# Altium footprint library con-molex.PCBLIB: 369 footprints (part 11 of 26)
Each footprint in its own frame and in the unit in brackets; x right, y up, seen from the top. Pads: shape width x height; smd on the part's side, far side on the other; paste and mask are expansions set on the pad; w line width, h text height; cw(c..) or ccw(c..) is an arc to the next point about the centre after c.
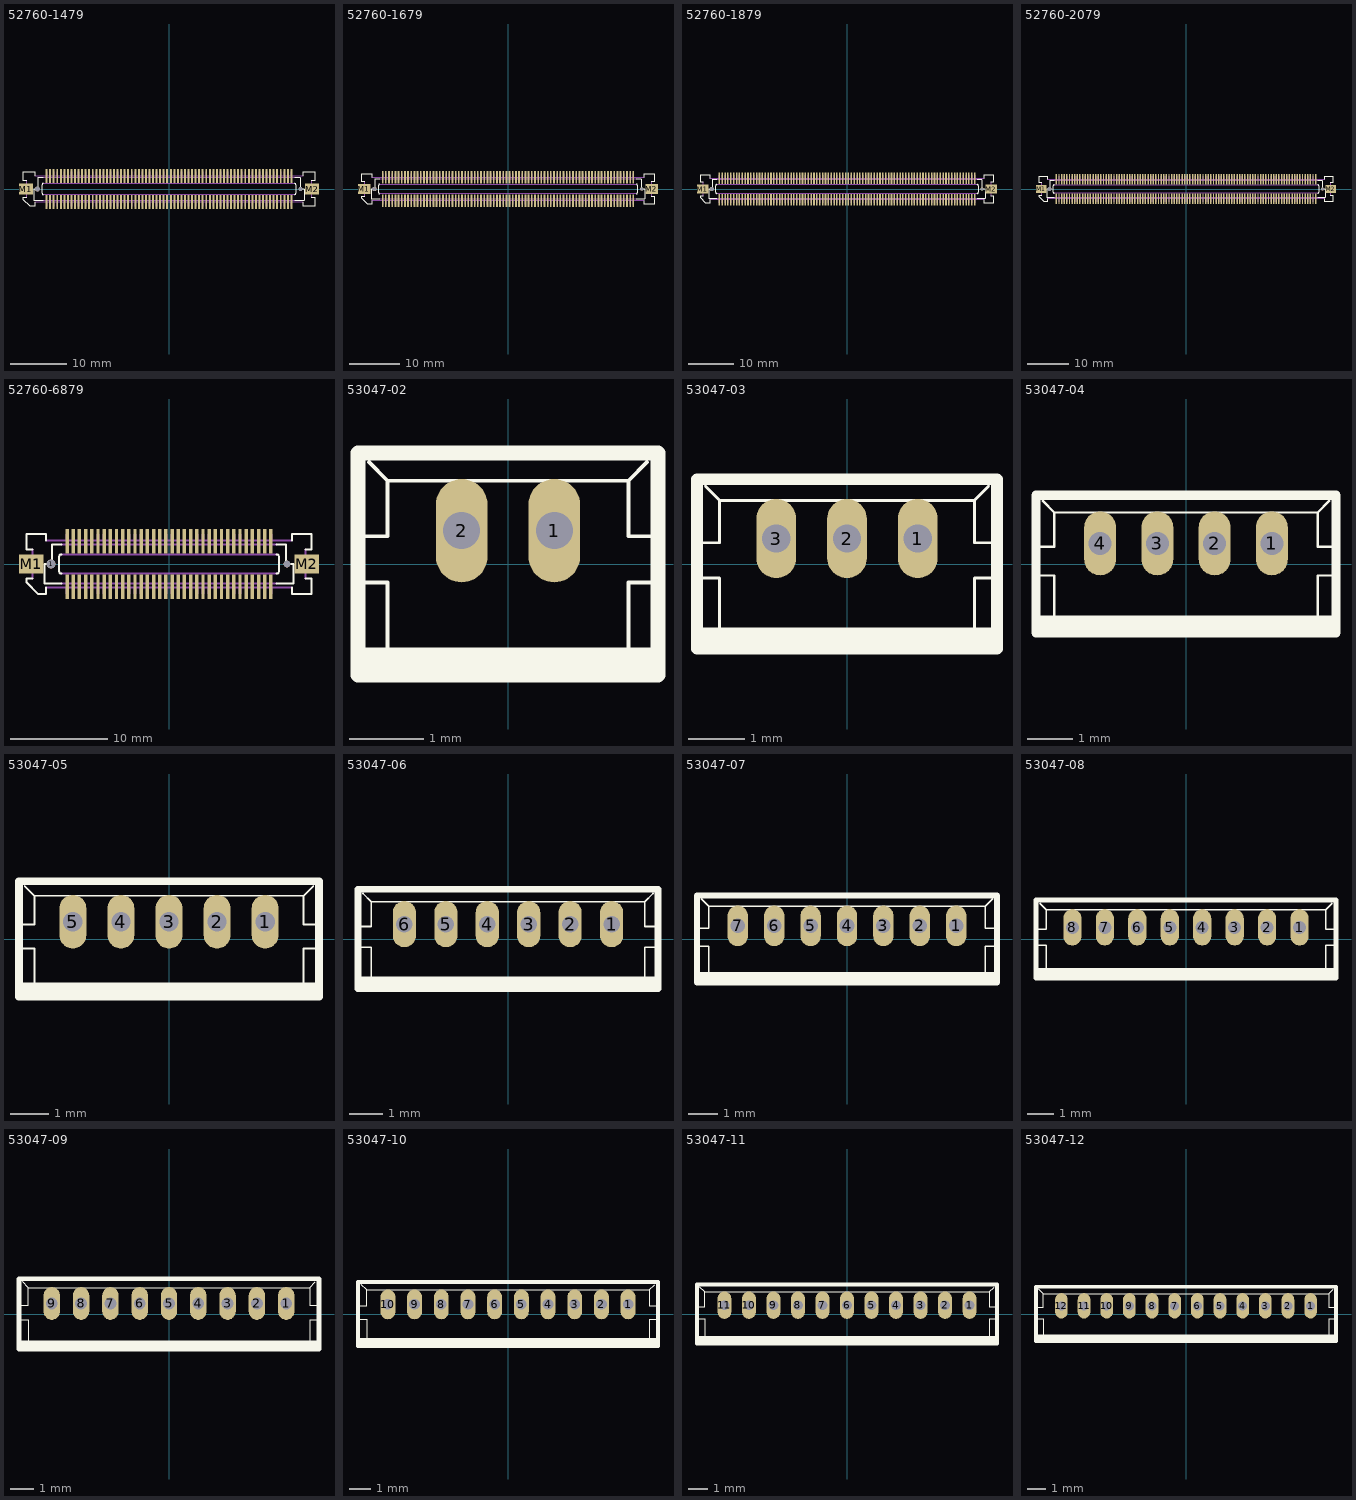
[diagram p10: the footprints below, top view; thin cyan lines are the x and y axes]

## 52760-1479 [mm]
pads (144):
  round 0.9 hole 0.9: 1(-23.56,0)
  rect 0.35x2.5 smd: 1(-21.907,-2.35) 2(-21.907,2.35) 3(-21.273,-2.35) 4(-21.273,2.35) 5(-20.637,-2.35) 6(-20.637,2.35) 7(-20.002,-2.35) 8(-20.002,2.35) 9(-19.367,-2.35) 10(-19.367,2.35) 11(-18.732,-2.35) 12(-18.732,2.35) 13(-18.098,-2.35) 14(-18.098,2.35) 15(-17.462,-2.35) 16(-17.462,2.35) 17(-16.828,-2.35) 18(-16.828,2.35) 19(-16.192,-2.35) 20(-16.192,2.35) 21(-15.557,-2.35) 22(-15.557,2.35) 23(-14.922,-2.35) 24(-14.922,2.35) 25(-14.287,-2.35) 26(-14.287,2.35) 27(-13.652,-2.35) 28(-13.652,2.35) 29(-13.018,-2.35) 30(-13.018,2.35) 31(-12.383,-2.35) 32(-12.383,2.35) 33(-11.747,-2.35) 34(-11.747,2.35) 35(-11.112,-2.35) 36(-11.112,2.35) 37(-10.477,-2.35) 38(-10.477,2.35) 39(-9.842,-2.35) 40(-9.842,2.35) 41(-9.207,-2.35) 42(-9.207,2.35) 43(-8.572,-2.35) 44(-8.572,2.35) 45(-7.938,-2.35) 46(-7.938,2.35) 47(-7.302,-2.35) 48(-7.302,2.35) 49(-6.667,-2.35) 50(-6.667,2.35) 51(-6.032,-2.35) 52(-6.032,2.35) 53(-5.397,-2.35) 54(-5.397,2.35) 55(-4.763,-2.35) 56(-4.763,2.35) 57(-4.127,-2.35) 58(-4.127,2.35) 59(-3.492,-2.35) 60(-3.492,2.35) 61(-2.857,-2.35) 62(-2.857,2.35) 63(-2.222,-2.35) 64(-2.222,2.35) 65(-1.587,-2.35) 66(-1.587,2.35) 67(-0.953,-2.35) 68(-0.953,2.35) 69(-0.318,-2.35) 70(-0.318,2.35) 71(0.318,-2.35) 72(0.318,2.35) 73(0.953,-2.35) 74(0.953,2.35) 75(1.587,-2.35) 76(1.587,2.35) 77(2.222,-2.35) 78(2.222,2.35) 79(2.857,-2.35) 80(2.857,2.35) 81(3.492,-2.35) 82(3.492,2.35) 83(4.127,-2.35) 84(4.127,2.35) 85(4.763,-2.35) 86(4.763,2.35) 87(5.397,-2.35) 88(5.397,2.35) 89(6.032,-2.35) 90(6.032,2.35) 91(6.667,-2.35) 92(6.667,2.35) 93(7.302,-2.35) 94(7.302,2.35) 95(7.938,-2.35) 96(7.938,2.35) 97(8.572,-2.35) 98(8.572,2.35) 99(9.207,-2.35) 100(9.207,2.35) 101(9.842,-2.35) 102(9.842,2.35) 103(10.477,-2.35) 104(10.477,2.35) 105(11.112,-2.35) 106(11.112,2.35) 107(11.747,-2.35) 108(11.747,2.35) 109(12.383,-2.35) 110(12.383,2.35) 111(13.018,-2.35) 112(13.018,2.35) 113(13.652,-2.35) 114(13.652,2.35) 115(14.287,-2.35) 116(14.287,2.35) 117(14.922,-2.35) 118(14.922,2.35) 119(15.557,-2.35) 120(15.557,2.35) 121(16.192,-2.35) 122(16.192,2.35) 123(16.828,-2.35) 124(16.828,2.35) 125(17.462,-2.35) 126(17.462,2.35) 127(18.098,-2.35) 128(18.098,2.35) 129(18.732,-2.35) 130(18.732,2.35) 131(19.367,-2.35) 132(19.367,2.35) 133(20.002,-2.35) 134(20.002,2.35) 135(20.637,-2.35) 136(20.637,2.35) 137(21.273,-2.35) 138(21.273,2.35) 139(21.907,-2.35) 140(21.907,2.35)
  round 0.7 hole 0.7: 1(23.56,0)
  rect 2.5x2 smd: M1(-25.6,0) M2(25.6,0)
Top Overlay:
  lines w0.203: -25.475,-1.5 -26.075,-1.5 -26.075,-1.9 -24.875,-3.1 -24.075,-3.1 -24.075,-2.4 ; -25.475,1.5 -26.075,1.5 -26.075,3.1 -24.075,3.1 -24.075,2.4 ; -22.475,-2 -24.225,-2 -24.225,0 -23.475,0 -23.475,2 -22.475,2 ; -22.475,-1 cw(c-22.475,-0.75) -22.725,-0.75 -22.725,0.75 cw(c-22.475,0.75) -22.475,1 ; 22.475,-2 24.225,-2 24.225,0 23.475,0 23.475,2 22.475,2 ; 22.475,-1 ccw(c22.475,-0.75) 22.725,-0.75 22.725,0.75 ccw(c22.475,0.75) 22.475,1 ; 24.075,-2.4 24.075,-3.1 26.075,-3.1 26.075,-1.5 25.475,-1.5 ; 24.075,2.4 24.075,3.1 26.075,3.1 26.075,1.5 25.475,1.5
Top Solder:
  rectangle: -22.107,-3.625 -21.708,-1.075
  region: -21.708,3.625 -22.107,3.625 -22.107,1.075 -21.708,1.075
  rectangle: -21.472,-3.625 -21.073,-1.075
  region: -21.073,3.625 -21.472,3.625 -21.472,1.075 -21.073,1.075
  rectangle: -20.837,-3.625 -20.438,-1.075
  region: -20.438,3.625 -20.837,3.625 -20.837,1.075 -20.438,1.075
  rectangle: -20.202,-3.625 -19.803,-1.075
  region: -19.803,3.625 -20.202,3.625 -20.202,1.075 -19.803,1.075
  rectangle: -19.567,-3.625 -19.168,-1.075
  region: -19.168,3.625 -19.567,3.625 -19.567,1.075 -19.168,1.075
  rectangle: -18.932,-3.625 -18.533,-1.075
  region: -18.533,3.625 -18.932,3.625 -18.932,1.075 -18.533,1.075
  rectangle: -18.297,-3.625 -17.898,-1.075
  region: -17.898,3.625 -18.297,3.625 -18.297,1.075 -17.898,1.075
  rectangle: -17.662,-3.625 -17.263,-1.075
  region: -17.263,3.625 -17.662,3.625 -17.662,1.075 -17.263,1.075
  rectangle: -17.027,-3.625 -16.628,-1.075
  region: -16.628,3.625 -17.027,3.625 -17.027,1.075 -16.628,1.075
  rectangle: -16.392,-3.625 -15.993,-1.075
  region: -15.993,3.625 -16.392,3.625 -16.392,1.075 -15.993,1.075
  rectangle: -15.757,-3.625 -15.358,-1.075
  region: -15.358,3.625 -15.757,3.625 -15.757,1.075 -15.358,1.075
  rectangle: -15.122,-3.625 -14.723,-1.075
  region: -14.723,3.625 -15.122,3.625 -15.122,1.075 -14.723,1.075
  rectangle: -14.487,-3.625 -14.088,-1.075
  region: -14.088,3.625 -14.487,3.625 -14.487,1.075 -14.088,1.075
  rectangle: -13.852,-3.625 -13.453,-1.075
  region: -13.453,3.625 -13.852,3.625 -13.852,1.075 -13.453,1.075
  rectangle: -13.217,-3.625 -12.818,-1.075
  region: -12.818,3.625 -13.217,3.625 -13.217,1.075 -12.818,1.075
  rectangle: -12.582,-3.625 -12.183,-1.075
  region: -12.183,3.625 -12.582,3.625 -12.582,1.075 -12.183,1.075
  rectangle: -11.947,-3.625 -11.548,-1.075
  region: -11.548,3.625 -11.947,3.625 -11.947,1.075 -11.548,1.075
  rectangle: -11.312,-3.625 -10.913,-1.075
  region: -10.913,3.625 -11.312,3.625 -11.312,1.075 -10.913,1.075
  rectangle: -10.677,-3.625 -10.278,-1.075
  region: -10.278,3.625 -10.677,3.625 -10.677,1.075 -10.278,1.075
  rectangle: -10.042,-3.625 -9.643,-1.075
  region: -9.643,3.625 -10.042,3.625 -10.042,1.075 -9.643,1.075
  rectangle: -9.407,-3.625 -9.008,-1.075
  region: -9.008,3.625 -9.407,3.625 -9.407,1.075 -9.008,1.075
  rectangle: -8.772,-3.625 -8.373,-1.075
  region: -8.373,3.625 -8.772,3.625 -8.772,1.075 -8.373,1.075
  rectangle: -8.137,-3.625 -7.738,-1.075
  region: -7.738,3.625 -8.137,3.625 -8.137,1.075 -7.738,1.075
  rectangle: -7.502,-3.625 -7.103,-1.075
  region: -7.103,3.625 -7.502,3.625 -7.502,1.075 -7.103,1.075
  rectangle: -6.867,-3.625 -6.468,-1.075
  region: -6.468,3.625 -6.867,3.625 -6.867,1.075 -6.468,1.075
  rectangle: -6.232,-3.625 -5.833,-1.075
  region: -5.833,3.625 -6.232,3.625 -6.232,1.075 -5.833,1.075
  rectangle: -5.597,-3.625 -5.198,-1.075
  region: -5.198,3.625 -5.597,3.625 -5.597,1.075 -5.198,1.075
  rectangle: -4.962,-3.625 -4.563,-1.075
  region: -4.563,3.625 -4.962,3.625 -4.962,1.075 -4.563,1.075
  rectangle: -4.327,-3.625 -3.928,-1.075
  region: -3.928,3.625 -4.327,3.625 -4.327,1.075 -3.928,1.075
  rectangle: -3.692,-3.625 -3.293,-1.075
  region: -3.293,3.625 -3.692,3.625 -3.692,1.075 -3.293,1.075
  rectangle: -3.057,-3.625 -2.658,-1.075
  region: -2.658,3.625 -3.057,3.625 -3.057,1.075 -2.658,1.075
  rectangle: -2.422,-3.625 -2.023,-1.075
  region: -2.023,3.625 -2.422,3.625 -2.422,1.075 -2.023,1.075
  rectangle: -1.787,-3.625 -1.388,-1.075
  region: -1.388,3.625 -1.787,3.625 -1.787,1.075 -1.388,1.075
  rectangle: -1.152,-3.625 -0.753,-1.075
  region: -0.753,3.625 -1.152,3.625 -1.152,1.075 -0.753,1.075
  rectangle: -0.517,-3.625 -0.118,-1.075
  region: -0.118,3.625 -0.517,3.625 -0.517,1.075 -0.118,1.075
  rectangle: 0.118,-3.625 0.517,-1.075
  region: 0.517,3.625 0.118,3.625 0.118,1.075 0.517,1.075
  rectangle: 0.753,-3.625 1.152,-1.075
  region: 1.152,3.625 0.753,3.625 0.753,1.075 1.152,1.075
  rectangle: 1.388,-3.625 1.787,-1.075
  region: 1.787,3.625 1.388,3.625 1.388,1.075 1.787,1.075
  rectangle: 2.023,-3.625 2.422,-1.075
  region: 2.422,3.625 2.023,3.625 2.023,1.075 2.422,1.075
  rectangle: 2.658,-3.625 3.057,-1.075
  region: 3.057,3.625 2.658,3.625 2.658,1.075 3.057,1.075
  rectangle: 3.293,-3.625 3.692,-1.075
  region: 3.692,3.625 3.293,3.625 3.293,1.075 3.692,1.075
  rectangle: 3.928,-3.625 4.327,-1.075
  region: 4.327,3.625 3.928,3.625 3.928,1.075 4.327,1.075
  rectangle: 4.563,-3.625 4.962,-1.075
  region: 4.962,3.625 4.563,3.625 4.563,1.075 4.962,1.075
  rectangle: 5.198,-3.625 5.597,-1.075
  region: 5.597,3.625 5.198,3.625 5.198,1.075 5.597,1.075
  rectangle: 5.833,-3.625 6.232,-1.075
  region: 6.232,3.625 5.833,3.625 5.833,1.075 6.232,1.075
  rectangle: 6.468,-3.625 6.867,-1.075
  region: 6.867,3.625 6.468,3.625 6.468,1.075 6.867,1.075
  rectangle: 7.103,-3.625 7.502,-1.075
  region: 7.502,3.625 7.103,3.625 7.103,1.075 7.502,1.075
  rectangle: 7.738,-3.625 8.137,-1.075
  region: 8.137,3.625 7.738,3.625 7.738,1.075 8.137,1.075
  rectangle: 8.373,-3.625 8.772,-1.075
  region: 8.772,3.625 8.373,3.625 8.373,1.075 8.772,1.075
  rectangle: 9.008,-3.625 9.407,-1.075
  region: 9.407,3.625 9.008,3.625 9.008,1.075 9.407,1.075
  rectangle: 9.643,-3.625 10.042,-1.075
  region: 10.042,3.625 9.643,3.625 9.643,1.075 10.042,1.075
  rectangle: 10.278,-3.625 10.677,-1.075
  region: 10.677,3.625 10.278,3.625 10.278,1.075 10.677,1.075
  rectangle: 10.913,-3.625 11.312,-1.075
  region: 11.312,3.625 10.913,3.625 10.913,1.075 11.312,1.075
  rectangle: 11.548,-3.625 11.947,-1.075
  region: 11.947,3.625 11.548,3.625 11.548,1.075 11.947,1.075
  rectangle: 12.183,-3.625 12.582,-1.075
  region: 12.582,3.625 12.183,3.625 12.183,1.075 12.582,1.075
  rectangle: 12.818,-3.625 13.217,-1.075
  region: 13.217,3.625 12.818,3.625 12.818,1.075 13.217,1.075
  rectangle: 13.453,-3.625 13.852,-1.075
  region: 13.852,3.625 13.453,3.625 13.453,1.075 13.852,1.075
  rectangle: 14.088,-3.625 14.487,-1.075
  region: 14.487,3.625 14.088,3.625 14.088,1.075 14.487,1.075
  rectangle: 14.723,-3.625 15.122,-1.075
  region: 15.122,3.625 14.723,3.625 14.723,1.075 15.122,1.075
  rectangle: 15.358,-3.625 15.757,-1.075
  region: 15.757,3.625 15.358,3.625 15.358,1.075 15.757,1.075
  rectangle: 15.993,-3.625 16.392,-1.075
  region: 16.392,3.625 15.993,3.625 15.993,1.075 16.392,1.075
  rectangle: 16.628,-3.625 17.027,-1.075
  region: 17.027,3.625 16.628,3.625 16.628,1.075 17.027,1.075
  rectangle: 17.263,-3.625 17.662,-1.075
  region: 17.662,3.625 17.263,3.625 17.263,1.075 17.662,1.075
  rectangle: 17.898,-3.625 18.297,-1.075
  region: 18.297,3.625 17.898,3.625 17.898,1.075 18.297,1.075
  rectangle: 18.533,-3.625 18.932,-1.075
  region: 18.932,3.625 18.533,3.625 18.533,1.075 18.932,1.075
  rectangle: 19.168,-3.625 19.567,-1.075
  region: 19.567,3.625 19.168,3.625 19.168,1.075 19.567,1.075
  rectangle: 19.803,-3.625 20.202,-1.075
  region: 20.202,3.625 19.803,3.625 19.803,1.075 20.202,1.075
  rectangle: 20.438,-3.625 20.837,-1.075
  region: 20.837,3.625 20.438,3.625 20.438,1.075 20.837,1.075
  rectangle: 21.073,-3.625 21.472,-1.075
  region: 21.472,3.625 21.073,3.625 21.073,1.075 21.472,1.075
  rectangle: 21.708,-3.625 22.107,-1.075
  region: 22.107,3.625 21.708,3.625 21.708,1.075 22.107,1.075
Mechanical 16:
  rectangle: -22.058,-3.1 -21.757,-2.375
  region: -21.757,3.1 -22.058,3.1 -22.058,2.375 -21.757,2.375
  rectangle: -21.423,-3.1 -21.122,-2.375
  region: -21.122,3.1 -21.423,3.1 -21.423,2.375 -21.122,2.375
  rectangle: -20.788,-3.1 -20.487,-2.375
  region: -20.487,3.1 -20.788,3.1 -20.788,2.375 -20.487,2.375
  rectangle: -20.153,-3.1 -19.852,-2.375
  region: -19.852,3.1 -20.153,3.1 -20.153,2.375 -19.852,2.375
  rectangle: -19.518,-3.1 -19.217,-2.375
  region: -19.217,3.1 -19.518,3.1 -19.518,2.375 -19.217,2.375
  rectangle: -18.883,-3.1 -18.582,-2.375
  region: -18.582,3.1 -18.883,3.1 -18.883,2.375 -18.582,2.375
  rectangle: -18.248,-3.1 -17.947,-2.375
  region: -17.947,3.1 -18.248,3.1 -18.248,2.375 -17.947,2.375
  rectangle: -17.613,-3.1 -17.312,-2.375
  region: -17.312,3.1 -17.613,3.1 -17.613,2.375 -17.312,2.375
  rectangle: -16.978,-3.1 -16.677,-2.375
  region: -16.677,3.1 -16.978,3.1 -16.978,2.375 -16.677,2.375
  rectangle: -16.343,-3.1 -16.042,-2.375
  region: -16.042,3.1 -16.343,3.1 -16.343,2.375 -16.042,2.375
  rectangle: -15.708,-3.1 -15.407,-2.375
  region: -15.407,3.1 -15.708,3.1 -15.708,2.375 -15.407,2.375
  rectangle: -15.073,-3.1 -14.772,-2.375
  region: -14.772,3.1 -15.073,3.1 -15.073,2.375 -14.772,2.375
  rectangle: -14.438,-3.1 -14.137,-2.375
  region: -14.137,3.1 -14.438,3.1 -14.438,2.375 -14.137,2.375
  rectangle: -13.803,-3.1 -13.502,-2.375
  region: -13.502,3.1 -13.803,3.1 -13.803,2.375 -13.502,2.375
  rectangle: -13.168,-3.1 -12.867,-2.375
  region: -12.867,3.1 -13.168,3.1 -13.168,2.375 -12.867,2.375
  rectangle: -12.533,-3.1 -12.232,-2.375
  region: -12.232,3.1 -12.533,3.1 -12.533,2.375 -12.232,2.375
  rectangle: -11.898,-3.1 -11.597,-2.375
  region: -11.597,3.1 -11.898,3.1 -11.898,2.375 -11.597,2.375
  rectangle: -11.263,-3.1 -10.962,-2.375
  region: -10.962,3.1 -11.263,3.1 -11.263,2.375 -10.962,2.375
  rectangle: -10.628,-3.1 -10.327,-2.375
  region: -10.327,3.1 -10.628,3.1 -10.628,2.375 -10.327,2.375
  rectangle: -9.993,-3.1 -9.692,-2.375
  region: -9.692,3.1 -9.993,3.1 -9.993,2.375 -9.692,2.375
  rectangle: -9.358,-3.1 -9.057,-2.375
  region: -9.057,3.1 -9.358,3.1 -9.358,2.375 -9.057,2.375
  rectangle: -8.723,-3.1 -8.422,-2.375
  region: -8.422,3.1 -8.723,3.1 -8.723,2.375 -8.422,2.375
  rectangle: -8.088,-3.1 -7.787,-2.375
  region: -7.787,3.1 -8.088,3.1 -8.088,2.375 -7.787,2.375
  rectangle: -7.453,-3.1 -7.152,-2.375
  region: -7.152,3.1 -7.453,3.1 -7.453,2.375 -7.152,2.375
  rectangle: -6.818,-3.1 -6.517,-2.375
  region: -6.517,3.1 -6.818,3.1 -6.818,2.375 -6.517,2.375
  rectangle: -6.183,-3.1 -5.882,-2.375
  region: -5.882,3.1 -6.183,3.1 -6.183,2.375 -5.882,2.375
  rectangle: -5.548,-3.1 -5.247,-2.375
  region: -5.247,3.1 -5.548,3.1 -5.548,2.375 -5.247,2.375
  rectangle: -4.913,-3.1 -4.612,-2.375
  region: -4.612,3.1 -4.913,3.1 -4.913,2.375 -4.612,2.375
  rectangle: -4.278,-3.1 -3.977,-2.375
  region: -3.977,3.1 -4.278,3.1 -4.278,2.375 -3.977,2.375
  rectangle: -3.643,-3.1 -3.342,-2.375
  region: -3.342,3.1 -3.643,3.1 -3.643,2.375 -3.342,2.375
  rectangle: -3.008,-3.1 -2.707,-2.375
  region: -2.707,3.1 -3.008,3.1 -3.008,2.375 -2.707,2.375
  rectangle: -2.373,-3.1 -2.072,-2.375
  region: -2.072,3.1 -2.373,3.1 -2.373,2.375 -2.072,2.375
  rectangle: -1.738,-3.1 -1.437,-2.375
  region: -1.437,3.1 -1.738,3.1 -1.738,2.375 -1.437,2.375
  rectangle: -1.103,-3.1 -0.802,-2.375
  region: -0.802,3.1 -1.103,3.1 -1.103,2.375 -0.802,2.375
  rectangle: -0.468,-3.1 -0.167,-2.375
  region: -0.167,3.1 -0.468,3.1 -0.468,2.375 -0.167,2.375
  rectangle: 0.167,-3.1 0.468,-2.375
  region: 0.468,3.1 0.167,3.1 0.167,2.375 0.468,2.375
  rectangle: 0.802,-3.1 1.103,-2.375
  region: 1.103,3.1 0.802,3.1 0.802,2.375 1.103,2.375
  rectangle: 1.437,-3.1 1.738,-2.375
  region: 1.738,3.1 1.437,3.1 1.437,2.375 1.738,2.375
  rectangle: 2.072,-3.1 2.373,-2.375
  region: 2.373,3.1 2.072,3.1 2.072,2.375 2.373,2.375
  rectangle: 2.707,-3.1 3.008,-2.375
  region: 3.008,3.1 2.707,3.1 2.707,2.375 3.008,2.375
  rectangle: 3.342,-3.1 3.643,-2.375
  region: 3.643,3.1 3.342,3.1 3.342,2.375 3.643,2.375
  rectangle: 3.977,-3.1 4.278,-2.375
  region: 4.278,3.1 3.977,3.1 3.977,2.375 4.278,2.375
  rectangle: 4.612,-3.1 4.913,-2.375
  region: 4.913,3.1 4.612,3.1 4.612,2.375 4.913,2.375
  rectangle: 5.247,-3.1 5.548,-2.375
  region: 5.548,3.1 5.247,3.1 5.247,2.375 5.548,2.375
  rectangle: 5.882,-3.1 6.183,-2.375
  region: 6.183,3.1 5.882,3.1 5.882,2.375 6.183,2.375
  rectangle: 6.517,-3.1 6.818,-2.375
  region: 6.818,3.1 6.517,3.1 6.517,2.375 6.818,2.375
  rectangle: 7.152,-3.1 7.453,-2.375
  region: 7.453,3.1 7.152,3.1 7.152,2.375 7.453,2.375
  rectangle: 7.787,-3.1 8.088,-2.375
  region: 8.088,3.1 7.787,3.1 7.787,2.375 8.088,2.375
  rectangle: 8.422,-3.1 8.723,-2.375
  region: 8.723,3.1 8.422,3.1 8.422,2.375 8.723,2.375
  rectangle: 9.057,-3.1 9.358,-2.375
  region: 9.358,3.1 9.057,3.1 9.057,2.375 9.358,2.375
  rectangle: 9.692,-3.1 9.993,-2.375
  region: 9.993,3.1 9.692,3.1 9.692,2.375 9.993,2.375
  rectangle: 10.327,-3.1 10.628,-2.375
  region: 10.628,3.1 10.327,3.1 10.327,2.375 10.628,2.375
  rectangle: 10.962,-3.1 11.263,-2.375
  region: 11.263,3.1 10.962,3.1 10.962,2.375 11.263,2.375
  rectangle: 11.597,-3.1 11.898,-2.375
  region: 11.898,3.1 11.597,3.1 11.597,2.375 11.898,2.375
  rectangle: 12.232,-3.1 12.533,-2.375
  region: 12.533,3.1 12.232,3.1 12.232,2.375 12.533,2.375
  rectangle: 12.867,-3.1 13.168,-2.375
  region: 13.168,3.1 12.867,3.1 12.867,2.375 13.168,2.375
  rectangle: 13.502,-3.1 13.803,-2.375
  region: 13.803,3.1 13.502,3.1 13.502,2.375 13.803,2.375
  rectangle: 14.137,-3.1 14.438,-2.375
  region: 14.438,3.1 14.137,3.1 14.137,2.375 14.438,2.375
  rectangle: 14.772,-3.1 15.073,-2.375
  region: 15.073,3.1 14.772,3.1 14.772,2.375 15.073,2.375
  rectangle: 15.407,-3.1 15.708,-2.375
  region: 15.708,3.1 15.407,3.1 15.407,2.375 15.708,2.375
  rectangle: 16.042,-3.1 16.343,-2.375
  region: 16.343,3.1 16.042,3.1 16.042,2.375 16.343,2.375
  rectangle: 16.677,-3.1 16.978,-2.375
  region: 16.978,3.1 16.677,3.1 16.677,2.375 16.978,2.375
  rectangle: 17.312,-3.1 17.613,-2.375
  region: 17.613,3.1 17.312,3.1 17.312,2.375 17.613,2.375
  rectangle: 17.947,-3.1 18.248,-2.375
  region: 18.248,3.1 17.947,3.1 17.947,2.375 18.248,2.375
  rectangle: 18.582,-3.1 18.883,-2.375
  region: 18.883,3.1 18.582,3.1 18.582,2.375 18.883,2.375
  rectangle: 19.217,-3.1 19.518,-2.375
  region: 19.518,3.1 19.217,3.1 19.217,2.375 19.518,2.375
  rectangle: 19.852,-3.1 20.153,-2.375
  region: 20.153,3.1 19.852,3.1 19.852,2.375 20.153,2.375
  rectangle: 20.487,-3.1 20.788,-2.375
  region: 20.788,3.1 20.487,3.1 20.487,2.375 20.788,2.375
  rectangle: 21.122,-3.1 21.423,-2.375
  region: 21.423,3.1 21.122,3.1 21.122,2.375 21.423,2.375
  rectangle: 21.757,-3.1 22.058,-2.375
  region: 22.058,3.1 21.757,3.1 21.757,2.375 22.058,2.375
  lines w0.203: -25.475,-1.5 -25.475,1.5 ; -24.075,-2.4 24.075,-2.4 ; -24.075,2.4 24.075,2.4 ; -22.475,-2 22.475,-2 ; -22.475,-1 22.475,-1 ; -22.475,1 22.475,1 ; -22.475,2 22.475,2 ; 25.475,-1.5 25.475,1.5

## 52760-1679 [mm]
pads (164):
  round 0.9 hole 0.9: 1(-26.735,0)
  rect 0.35x2.5 smd: 1(-25.082,-2.35) 2(-25.082,2.35) 3(-24.447,-2.35) 4(-24.447,2.35) 5(-23.812,-2.35) 6(-23.812,2.35) 7(-23.177,-2.35) 8(-23.177,2.35) 9(-22.543,-2.35) 10(-22.543,2.35) 11(-21.907,-2.35) 12(-21.907,2.35) 13(-21.273,-2.35) 14(-21.273,2.35) 15(-20.637,-2.35) 16(-20.637,2.35) 17(-20.002,-2.35) 18(-20.002,2.35) 19(-19.367,-2.35) 20(-19.367,2.35) 21(-18.732,-2.35) 22(-18.732,2.35) 23(-18.098,-2.35) 24(-18.098,2.35) 25(-17.462,-2.35) 26(-17.462,2.35) 27(-16.828,-2.35) 28(-16.828,2.35) 29(-16.192,-2.35) 30(-16.192,2.35) 31(-15.557,-2.35) 32(-15.557,2.35) 33(-14.922,-2.35) 34(-14.922,2.35) 35(-14.287,-2.35) 36(-14.287,2.35) 37(-13.652,-2.35) 38(-13.652,2.35) 39(-13.018,-2.35) 40(-13.018,2.35) 41(-12.383,-2.35) 42(-12.383,2.35) 43(-11.747,-2.35) 44(-11.747,2.35) 45(-11.112,-2.35) 46(-11.112,2.35) 47(-10.477,-2.35) 48(-10.477,2.35) 49(-9.842,-2.35) 50(-9.842,2.35) 51(-9.207,-2.35) 52(-9.207,2.35) 53(-8.572,-2.35) 54(-8.572,2.35) 55(-7.938,-2.35) 56(-7.938,2.35) 57(-7.302,-2.35) 58(-7.302,2.35) 59(-6.667,-2.35) 60(-6.667,2.35) 61(-6.032,-2.35) 62(-6.032,2.35) 63(-5.397,-2.35) 64(-5.397,2.35) 65(-4.763,-2.35) 66(-4.763,2.35) 67(-4.127,-2.35) 68(-4.127,2.35) 69(-3.492,-2.35) 70(-3.492,2.35) 71(-2.857,-2.35) 72(-2.857,2.35) 73(-2.222,-2.35) 74(-2.222,2.35) 75(-1.587,-2.35) 76(-1.587,2.35) 77(-0.953,-2.35) 78(-0.953,2.35) 79(-0.318,-2.35) 80(-0.318,2.35) 81(0.318,-2.35) 82(0.318,2.35) 83(0.953,-2.35) 84(0.953,2.35) 85(1.587,-2.35) 86(1.587,2.35) 87(2.222,-2.35) 88(2.222,2.35) 89(2.857,-2.35) 90(2.857,2.35) 91(3.492,-2.35) 92(3.492,2.35) 93(4.127,-2.35) 94(4.127,2.35) 95(4.763,-2.35) 96(4.763,2.35) 97(5.397,-2.35) 98(5.397,2.35) 99(6.032,-2.35) 100(6.032,2.35) 101(6.667,-2.35) 102(6.667,2.35) 103(7.302,-2.35) 104(7.302,2.35) 105(7.938,-2.35) 106(7.938,2.35) 107(8.572,-2.35) 108(8.572,2.35) 109(9.207,-2.35) 110(9.207,2.35) 111(9.842,-2.35) 112(9.842,2.35) 113(10.477,-2.35) 114(10.477,2.35) 115(11.112,-2.35) 116(11.112,2.35) 117(11.747,-2.35) 118(11.747,2.35) 119(12.383,-2.35) 120(12.383,2.35) 121(13.018,-2.35) 122(13.018,2.35) 123(13.652,-2.35) 124(13.652,2.35) 125(14.287,-2.35) 126(14.287,2.35) 127(14.922,-2.35) 128(14.922,2.35) 129(15.557,-2.35) 130(15.557,2.35) 131(16.192,-2.35) 132(16.192,2.35) 133(16.828,-2.35) 134(16.828,2.35) 135(17.462,-2.35) 136(17.462,2.35) 137(18.098,-2.35) 138(18.098,2.35) 139(18.732,-2.35) 140(18.732,2.35) 141(19.367,-2.35) 142(19.367,2.35) 143(20.002,-2.35) 144(20.002,2.35) 145(20.637,-2.35) 146(20.637,2.35) 147(21.273,-2.35) 148(21.273,2.35) 149(21.907,-2.35) 150(21.907,2.35) 151(22.543,-2.35) 152(22.543,2.35) 153(23.177,-2.35) 154(23.177,2.35) 155(23.812,-2.35) 156(23.812,2.35) 157(24.447,-2.35) 158(24.447,2.35) 159(25.082,-2.35) 160(25.082,2.35)
  round 0.7 hole 0.7: 1(26.735,0)
  rect 2.5x2 smd: M1(-28.775,0) M2(28.775,0)
Top Overlay:
  lines w0.203: -28.65,-1.5 -29.25,-1.5 -29.25,-1.9 -28.05,-3.1 -27.25,-3.1 -27.25,-2.4 ; -28.65,1.5 -29.25,1.5 -29.25,3.1 -27.25,3.1 -27.25,2.4 ; -25.65,-2 -27.4,-2 -27.4,0 -26.65,0 -26.65,2 -25.65,2 ; -25.65,-1 cw(c-25.65,-0.75) -25.9,-0.75 -25.9,0.75 cw(c-25.65,0.75) -25.65,1 ; 25.65,-2 27.4,-2 27.4,0 26.65,0 26.65,2 25.65,2 ; 25.65,-1 ccw(c25.65,-0.75) 25.9,-0.75 25.9,0.75 ccw(c25.65,0.75) 25.65,1 ; 27.25,-2.4 27.25,-3.1 29.25,-3.1 29.25,-1.5 28.65,-1.5 ; 27.25,2.4 27.25,3.1 29.25,3.1 29.25,1.5 28.65,1.5
Top Solder:
  drawing of 160 lines, arcs and shapes, not listed
Mechanical 16:
  drawing of 168 lines, arcs and shapes, not listed

## 52760-1879 [mm]
pads (184):
  round 0.9 hole 0.9: 1(-29.91,0)
  rect 0.35x2.5 smd: 1(-28.258,-2.35) 2(-28.258,2.35) 3(-27.622,-2.35) 4(-27.622,2.35) 5(-26.987,-2.35) 6(-26.987,2.35) 7(-26.352,-2.35) 8(-26.352,2.35) 9(-25.717,-2.35) 10(-25.717,2.35) 11(-25.082,-2.35) 12(-25.082,2.35) 13(-24.447,-2.35) 14(-24.447,2.35) 15(-23.812,-2.35) 16(-23.812,2.35) 17(-23.177,-2.35) 18(-23.177,2.35) 19(-22.543,-2.35) 20(-22.543,2.35) 21(-21.907,-2.35) 22(-21.907,2.35) 23(-21.273,-2.35) 24(-21.273,2.35) 25(-20.637,-2.35) 26(-20.637,2.35) 27(-20.002,-2.35) 28(-20.002,2.35) 29(-19.367,-2.35) 30(-19.367,2.35) 31(-18.732,-2.35) 32(-18.732,2.35) 33(-18.098,-2.35) 34(-18.098,2.35) 35(-17.462,-2.35) 36(-17.462,2.35) 37(-16.828,-2.35) 38(-16.828,2.35) 39(-16.192,-2.35) 40(-16.192,2.35) 41(-15.557,-2.35) 42(-15.557,2.35) 43(-14.922,-2.35) 44(-14.922,2.35) 45(-14.287,-2.35) 46(-14.287,2.35) 47(-13.652,-2.35) 48(-13.652,2.35) 49(-13.018,-2.35) 50(-13.018,2.35) 51(-12.383,-2.35) 52(-12.383,2.35) 53(-11.747,-2.35) 54(-11.747,2.35) 55(-11.112,-2.35) 56(-11.112,2.35) 57(-10.477,-2.35) 58(-10.477,2.35) 59(-9.842,-2.35) 60(-9.842,2.35) 61(-9.207,-2.35) 62(-9.207,2.35) 63(-8.572,-2.35) 64(-8.572,2.35) 65(-7.938,-2.35) 66(-7.938,2.35) 67(-7.302,-2.35) 68(-7.302,2.35) 69(-6.667,-2.35) 70(-6.667,2.35) 71(-6.032,-2.35) 72(-6.032,2.35) 73(-5.397,-2.35) 74(-5.397,2.35) 75(-4.763,-2.35) 76(-4.763,2.35) 77(-4.127,-2.35) 78(-4.127,2.35) 79(-3.492,-2.35) 80(-3.492,2.35) 81(-2.857,-2.35) 82(-2.857,2.35) 83(-2.222,-2.35) 84(-2.222,2.35) 85(-1.587,-2.35) 86(-1.587,2.35) 87(-0.953,-2.35) 88(-0.953,2.35) 89(-0.318,-2.35) 90(-0.318,2.35) 91(0.318,-2.35) 92(0.318,2.35) 93(0.953,-2.35) 94(0.953,2.35) 95(1.587,-2.35) 96(1.587,2.35) 97(2.222,-2.35) 98(2.222,2.35) 99(2.857,-2.35) 100(2.857,2.35) 101(3.492,-2.35) 102(3.492,2.35) 103(4.127,-2.35) 104(4.127,2.35) 105(4.763,-2.35) 106(4.763,2.35) 107(5.397,-2.35) 108(5.397,2.35) 109(6.032,-2.35) 110(6.032,2.35) 111(6.667,-2.35) 112(6.667,2.35) 113(7.302,-2.35) 114(7.302,2.35) 115(7.938,-2.35) 116(7.938,2.35) 117(8.572,-2.35) 118(8.572,2.35) 119(9.207,-2.35) 120(9.207,2.35) 121(9.842,-2.35) 122(9.842,2.35) 123(10.477,-2.35) 124(10.477,2.35) 125(11.112,-2.35) 126(11.112,2.35) 127(11.747,-2.35) 128(11.747,2.35) 129(12.383,-2.35) 130(12.383,2.35) 131(13.018,-2.35) 132(13.018,2.35) 133(13.652,-2.35) 134(13.652,2.35) 135(14.287,-2.35) 136(14.287,2.35) 137(14.922,-2.35) 138(14.922,2.35) 139(15.557,-2.35) 140(15.557,2.35) 141(16.192,-2.35) 142(16.192,2.35) 143(16.828,-2.35) 144(16.828,2.35) 145(17.462,-2.35) 146(17.462,2.35) 147(18.098,-2.35) 148(18.098,2.35) 149(18.732,-2.35) 150(18.732,2.35) 151(19.367,-2.35) 152(19.367,2.35) 153(20.002,-2.35) 154(20.002,2.35) 155(20.637,-2.35) 156(20.637,2.35) 157(21.273,-2.35) 158(21.273,2.35) 159(21.907,-2.35) 160(21.907,2.35) 161(22.543,-2.35) 162(22.543,2.35) 163(23.177,-2.35) 164(23.177,2.35) 165(23.812,-2.35) 166(23.812,2.35) 167(24.447,-2.35) 168(24.447,2.35) 169(25.082,-2.35) 170(25.082,2.35) 171(25.717,-2.35) 172(25.717,2.35) 173(26.352,-2.35) 174(26.352,2.35) 175(26.987,-2.35) 176(26.987,2.35) 177(27.622,-2.35) 178(27.622,2.35) 179(28.258,-2.35) 180(28.258,2.35)
  round 0.7 hole 0.7: 1(29.91,0)
  rect 2.5x2 smd: M1(-31.95,0) M2(31.95,0)
Top Overlay:
  lines w0.203: -31.825,-1.5 -32.425,-1.5 -32.425,-1.9 -31.225,-3.1 -30.425,-3.1 -30.425,-2.4 ; -31.825,1.5 -32.425,1.5 -32.425,3.1 -30.425,3.1 -30.425,2.4 ; -28.825,-2 -30.575,-2 -30.575,0 -29.825,0 -29.825,2 -28.825,2 ; -28.825,-1 cw(c-28.825,-0.75) -29.075,-0.75 -29.075,0.75 cw(c-28.825,0.75) -28.825,1 ; 28.825,-2 30.575,-2 30.575,0 29.825,0 29.825,2 28.825,2 ; 28.825,-1 ccw(c28.825,-0.75) 29.075,-0.75 29.075,0.75 ccw(c28.825,0.75) 28.825,1 ; 30.425,-2.4 30.425,-3.1 32.425,-3.1 32.425,-1.5 31.825,-1.5 ; 30.425,2.4 30.425,3.1 32.425,3.1 32.425,1.5 31.825,1.5
Top Solder:
  drawing of 180 lines, arcs and shapes, not listed
Mechanical 16:
  drawing of 188 lines, arcs and shapes, not listed

## 52760-2079 [mm]
pads (204):
  round 0.9 hole 0.9: 1(-33.085,0)
  rect 0.35x2.5 smd: 1(-31.432,-2.35) 2(-31.432,2.35) 3(-30.797,-2.35) 4(-30.797,2.35) 5(-30.162,-2.35) 6(-30.162,2.35) 7(-29.527,-2.35) 8(-29.527,2.35) 9(-28.892,-2.35) 10(-28.892,2.35) 11(-28.258,-2.35) 12(-28.258,2.35) 13(-27.622,-2.35) 14(-27.622,2.35) 15(-26.987,-2.35) 16(-26.987,2.35) 17(-26.352,-2.35) 18(-26.352,2.35) 19(-25.717,-2.35) 20(-25.717,2.35) 21(-25.082,-2.35) 22(-25.082,2.35) 23(-24.447,-2.35) 24(-24.447,2.35) 25(-23.812,-2.35) 26(-23.812,2.35) 27(-23.177,-2.35) 28(-23.177,2.35) 29(-22.543,-2.35) 30(-22.543,2.35) 31(-21.907,-2.35) 32(-21.907,2.35) 33(-21.273,-2.35) 34(-21.273,2.35) 35(-20.637,-2.35) 36(-20.637,2.35) 37(-20.002,-2.35) 38(-20.002,2.35) 39(-19.367,-2.35) 40(-19.367,2.35) 41(-18.732,-2.35) 42(-18.732,2.35) 43(-18.098,-2.35) 44(-18.098,2.35) 45(-17.462,-2.35) 46(-17.462,2.35) 47(-16.828,-2.35) 48(-16.828,2.35) 49(-16.192,-2.35) 50(-16.192,2.35) 51(-15.557,-2.35) 52(-15.557,2.35) 53(-14.922,-2.35) 54(-14.922,2.35) 55(-14.287,-2.35) 56(-14.287,2.35) 57(-13.652,-2.35) 58(-13.652,2.35) 59(-13.018,-2.35) 60(-13.018,2.35) 61(-12.383,-2.35) 62(-12.383,2.35) 63(-11.747,-2.35) 64(-11.747,2.35) 65(-11.112,-2.35) 66(-11.112,2.35) 67(-10.477,-2.35) 68(-10.477,2.35) 69(-9.842,-2.35) 70(-9.842,2.35) 71(-9.207,-2.35) 72(-9.207,2.35) 73(-8.572,-2.35) 74(-8.572,2.35) 75(-7.938,-2.35) 76(-7.938,2.35) 77(-7.302,-2.35) 78(-7.302,2.35) 79(-6.667,-2.35) 80(-6.667,2.35) 81(-6.032,-2.35) 82(-6.032,2.35) 83(-5.397,-2.35) 84(-5.397,2.35) 85(-4.763,-2.35) 86(-4.763,2.35) 87(-4.127,-2.35) 88(-4.127,2.35) 89(-3.492,-2.35) 90(-3.492,2.35) 91(-2.857,-2.35) 92(-2.857,2.35) 93(-2.222,-2.35) 94(-2.222,2.35) 95(-1.587,-2.35) 96(-1.587,2.35) 97(-0.953,-2.35) 98(-0.953,2.35) 99(-0.318,-2.35) 100(-0.318,2.35) 101(0.318,-2.35) 102(0.318,2.35) 103(0.953,-2.35) 104(0.953,2.35) 105(1.587,-2.35) 106(1.587,2.35) 107(2.222,-2.35) 108(2.222,2.35) 109(2.857,-2.35) 110(2.857,2.35) 111(3.492,-2.35) 112(3.492,2.35) 113(4.127,-2.35) 114(4.127,2.35) 115(4.763,-2.35) 116(4.763,2.35) 117(5.397,-2.35) 118(5.397,2.35) 119(6.032,-2.35) 120(6.032,2.35) 121(6.667,-2.35) 122(6.667,2.35) 123(7.302,-2.35) 124(7.302,2.35) 125(7.938,-2.35) 126(7.938,2.35) 127(8.572,-2.35) 128(8.572,2.35) 129(9.207,-2.35) 130(9.207,2.35) 131(9.842,-2.35) 132(9.842,2.35) 133(10.477,-2.35) 134(10.477,2.35) 135(11.112,-2.35) 136(11.112,2.35) 137(11.747,-2.35) 138(11.747,2.35) 139(12.383,-2.35) 140(12.383,2.35) 141(13.018,-2.35) 142(13.018,2.35) 143(13.652,-2.35) 144(13.652,2.35) 145(14.287,-2.35) 146(14.287,2.35) 147(14.922,-2.35) 148(14.922,2.35) 149(15.557,-2.35) 150(15.557,2.35) 151(16.192,-2.35) 152(16.192,2.35) 153(16.828,-2.35) 154(16.828,2.35) 155(17.462,-2.35) 156(17.462,2.35) 157(18.098,-2.35) 158(18.098,2.35) 159(18.732,-2.35) 160(18.732,2.35) 161(19.367,-2.35) 162(19.367,2.35) 163(20.002,-2.35) 164(20.002,2.35) 165(20.637,-2.35) 166(20.637,2.35) 167(21.273,-2.35) 168(21.273,2.35) 169(21.907,-2.35) 170(21.907,2.35) 171(22.543,-2.35) 172(22.543,2.35) 173(23.177,-2.35) 174(23.177,2.35) 175(23.812,-2.35) 176(23.812,2.35) 177(24.447,-2.35) 178(24.447,2.35) 179(25.082,-2.35) 180(25.082,2.35) 181(25.717,-2.35) 182(25.717,2.35) 183(26.352,-2.35) 184(26.352,2.35) 185(26.987,-2.35) 186(26.987,2.35) 187(27.622,-2.35) 188(27.622,2.35) 189(28.258,-2.35) 190(28.258,2.35) 191(28.892,-2.35) 192(28.892,2.35) 193(29.527,-2.35) 194(29.527,2.35) 195(30.162,-2.35) 196(30.162,2.35) 197(30.797,-2.35) 198(30.797,2.35) 199(31.432,-2.35) 200(31.432,2.35)
  round 0.7 hole 0.7: 1(33.085,0)
  rect 2.5x2 smd: M1(-35.125,0) M2(35.125,0)
Top Overlay:
  lines w0.203: -35,-1.5 -35.6,-1.5 -35.6,-1.9 -34.4,-3.1 -33.6,-3.1 -33.6,-2.4 ; -35,1.5 -35.6,1.5 -35.6,3.1 -33.6,3.1 -33.6,2.4 ; -32,-2 -33.75,-2 -33.75,0 -33,0 -33,2 -32,2 ; -32,-1 cw(c-32,-0.75) -32.25,-0.75 -32.25,0.75 cw(c-32,0.75) -32,1 ; 32,-2 33.75,-2 33.75,0 33,0 33,2 32,2 ; 32,-1 ccw(c32,-0.75) 32.25,-0.75 32.25,0.75 ccw(c32,0.75) 32,1 ; 33.6,-2.4 33.6,-3.1 35.6,-3.1 35.6,-1.5 35,-1.5 ; 33.6,2.4 33.6,3.1 35.6,3.1 35.6,1.5 35,1.5
Top Solder:
  drawing of 200 lines, arcs and shapes, not listed
Mechanical 16:
  drawing of 208 lines, arcs and shapes, not listed

## 52760-6879 [mm]
pads (72):
  round 0.9 hole 0.9: 1(-12.13,0)
  rect 0.35x2.5 smd: 1(-10.477,-2.35) 2(-10.477,2.35) 3(-9.842,-2.35) 4(-9.842,2.35) 5(-9.207,-2.35) 6(-9.207,2.35) 7(-8.572,-2.35) 8(-8.572,2.35) 9(-7.938,-2.35) 10(-7.938,2.35) 11(-7.302,-2.35) 12(-7.302,2.35) 13(-6.667,-2.35) 14(-6.667,2.35) 15(-6.032,-2.35) 16(-6.032,2.35) 17(-5.397,-2.35) 18(-5.397,2.35) 19(-4.763,-2.35) 20(-4.763,2.35) 21(-4.127,-2.35) 22(-4.127,2.35) 23(-3.492,-2.35) 24(-3.492,2.35) 25(-2.857,-2.35) 26(-2.857,2.35) 27(-2.222,-2.35) 28(-2.222,2.35) 29(-1.587,-2.35) 30(-1.587,2.35) 31(-0.953,-2.35) 32(-0.953,2.35) 33(-0.318,-2.35) 34(-0.318,2.35) 35(0.318,-2.35) 36(0.318,2.35) 37(0.953,-2.35) 38(0.953,2.35) 39(1.587,-2.35) 40(1.587,2.35) 41(2.222,-2.35) 42(2.222,2.35) 43(2.857,-2.35) 44(2.857,2.35) 45(3.492,-2.35) 46(3.492,2.35) 47(4.127,-2.35) 48(4.127,2.35) 49(4.763,-2.35) 50(4.763,2.35) 51(5.397,-2.35) 52(5.397,2.35) 53(6.032,-2.35) 54(6.032,2.35) 55(6.667,-2.35) 56(6.667,2.35) 57(7.302,-2.35) 58(7.302,2.35) 59(7.938,-2.35) 60(7.938,2.35) 61(8.572,-2.35) 62(8.572,2.35) 63(9.207,-2.35) 64(9.207,2.35) 65(9.842,-2.35) 66(9.842,2.35) 67(10.477,-2.35) 68(10.477,2.35)
  round 0.7 hole 0.7: 1(12.13,0)
  rect 2.5x2 smd: M1(-14.17,0) M2(14.17,0)
Top Overlay:
  lines w0.203: -14.045,-1.5 -14.645,-1.5 -14.645,-1.9 -13.445,-3.1 -12.645,-3.1 -12.645,-2.4 ; -14.045,1.5 -14.645,1.5 -14.645,3.1 -12.645,3.1 -12.645,2.4 ; -11.045,-2 -12.795,-2 -12.795,0 -12.045,0 -12.045,2 -11.045,2 ; -11.045,-1 cw(c-11.045,-0.75) -11.295,-0.75 -11.295,0.75 cw(c-11.045,0.75) -11.045,1 ; 11.045,-2 12.795,-2 12.795,0 12.045,0 12.045,2 11.045,2 ; 11.045,-1 ccw(c11.045,-0.75) 11.295,-0.75 11.295,0.75 ccw(c11.045,0.75) 11.045,1 ; 12.645,-2.4 12.645,-3.1 14.645,-3.1 14.645,-1.5 14.045,-1.5 ; 12.645,2.4 12.645,3.1 14.645,3.1 14.645,1.5 14.045,1.5
Top Solder:
  rectangle: -10.677,-3.625 -10.278,-1.075
  region: -10.278,3.625 -10.677,3.625 -10.677,1.075 -10.278,1.075
  rectangle: -10.042,-3.625 -9.643,-1.075
  region: -9.643,3.625 -10.042,3.625 -10.042,1.075 -9.643,1.075
  rectangle: -9.407,-3.625 -9.008,-1.075
  region: -9.008,3.625 -9.407,3.625 -9.407,1.075 -9.008,1.075
  rectangle: -8.772,-3.625 -8.373,-1.075
  region: -8.373,3.625 -8.772,3.625 -8.772,1.075 -8.373,1.075
  rectangle: -8.137,-3.625 -7.738,-1.075
  region: -7.738,3.625 -8.137,3.625 -8.137,1.075 -7.738,1.075
  rectangle: -7.502,-3.625 -7.103,-1.075
  region: -7.103,3.625 -7.502,3.625 -7.502,1.075 -7.103,1.075
  rectangle: -6.867,-3.625 -6.468,-1.075
  region: -6.468,3.625 -6.867,3.625 -6.867,1.075 -6.468,1.075
  rectangle: -6.232,-3.625 -5.833,-1.075
  region: -5.833,3.625 -6.232,3.625 -6.232,1.075 -5.833,1.075
  rectangle: -5.597,-3.625 -5.198,-1.075
  region: -5.198,3.625 -5.597,3.625 -5.597,1.075 -5.198,1.075
  rectangle: -4.962,-3.625 -4.563,-1.075
  region: -4.563,3.625 -4.962,3.625 -4.962,1.075 -4.563,1.075
  rectangle: -4.327,-3.625 -3.928,-1.075
  region: -3.928,3.625 -4.327,3.625 -4.327,1.075 -3.928,1.075
  rectangle: -3.692,-3.625 -3.293,-1.075
  region: -3.293,3.625 -3.692,3.625 -3.692,1.075 -3.293,1.075
  rectangle: -3.057,-3.625 -2.658,-1.075
  region: -2.658,3.625 -3.057,3.625 -3.057,1.075 -2.658,1.075
  rectangle: -2.422,-3.625 -2.023,-1.075
  region: -2.023,3.625 -2.422,3.625 -2.422,1.075 -2.023,1.075
  rectangle: -1.787,-3.625 -1.388,-1.075
  region: -1.388,3.625 -1.787,3.625 -1.787,1.075 -1.388,1.075
  rectangle: -1.152,-3.625 -0.753,-1.075
  region: -0.753,3.625 -1.152,3.625 -1.152,1.075 -0.753,1.075
  rectangle: -0.517,-3.625 -0.118,-1.075
  region: -0.118,3.625 -0.517,3.625 -0.517,1.075 -0.118,1.075
  rectangle: 0.118,-3.625 0.517,-1.075
  region: 0.517,3.625 0.118,3.625 0.118,1.075 0.517,1.075
  rectangle: 0.753,-3.625 1.152,-1.075
  region: 1.152,3.625 0.753,3.625 0.753,1.075 1.152,1.075
  rectangle: 1.388,-3.625 1.787,-1.075
  region: 1.787,3.625 1.388,3.625 1.388,1.075 1.787,1.075
  rectangle: 2.023,-3.625 2.422,-1.075
  region: 2.422,3.625 2.023,3.625 2.023,1.075 2.422,1.075
  rectangle: 2.658,-3.625 3.057,-1.075
  region: 3.057,3.625 2.658,3.625 2.658,1.075 3.057,1.075
  rectangle: 3.293,-3.625 3.692,-1.075
  region: 3.692,3.625 3.293,3.625 3.293,1.075 3.692,1.075
  rectangle: 3.928,-3.625 4.327,-1.075
  region: 4.327,3.625 3.928,3.625 3.928,1.075 4.327,1.075
  rectangle: 4.563,-3.625 4.962,-1.075
  region: 4.962,3.625 4.563,3.625 4.563,1.075 4.962,1.075
  rectangle: 5.198,-3.625 5.597,-1.075
  region: 5.597,3.625 5.198,3.625 5.198,1.075 5.597,1.075
  rectangle: 5.833,-3.625 6.232,-1.075
  region: 6.232,3.625 5.833,3.625 5.833,1.075 6.232,1.075
  rectangle: 6.468,-3.625 6.867,-1.075
  region: 6.867,3.625 6.468,3.625 6.468,1.075 6.867,1.075
  rectangle: 7.103,-3.625 7.502,-1.075
  region: 7.502,3.625 7.103,3.625 7.103,1.075 7.502,1.075
  rectangle: 7.738,-3.625 8.137,-1.075
  region: 8.137,3.625 7.738,3.625 7.738,1.075 8.137,1.075
  rectangle: 8.373,-3.625 8.772,-1.075
  region: 8.772,3.625 8.373,3.625 8.373,1.075 8.772,1.075
  rectangle: 9.008,-3.625 9.407,-1.075
  region: 9.407,3.625 9.008,3.625 9.008,1.075 9.407,1.075
  rectangle: 9.643,-3.625 10.042,-1.075
  region: 10.042,3.625 9.643,3.625 9.643,1.075 10.042,1.075
  rectangle: 10.278,-3.625 10.677,-1.075
  region: 10.677,3.625 10.278,3.625 10.278,1.075 10.677,1.075
Mechanical 16:
  rectangle: -10.628,-3.1 -10.327,-2.375
  region: -10.327,3.1 -10.628,3.1 -10.628,2.375 -10.327,2.375
  rectangle: -9.993,-3.1 -9.692,-2.375
  region: -9.692,3.1 -9.993,3.1 -9.993,2.375 -9.692,2.375
  rectangle: -9.358,-3.1 -9.057,-2.375
  region: -9.057,3.1 -9.358,3.1 -9.358,2.375 -9.057,2.375
  rectangle: -8.723,-3.1 -8.422,-2.375
  region: -8.422,3.1 -8.723,3.1 -8.723,2.375 -8.422,2.375
  rectangle: -8.088,-3.1 -7.787,-2.375
  region: -7.787,3.1 -8.088,3.1 -8.088,2.375 -7.787,2.375
  rectangle: -7.453,-3.1 -7.152,-2.375
  region: -7.152,3.1 -7.453,3.1 -7.453,2.375 -7.152,2.375
  rectangle: -6.818,-3.1 -6.517,-2.375
  region: -6.517,3.1 -6.818,3.1 -6.818,2.375 -6.517,2.375
  rectangle: -6.183,-3.1 -5.882,-2.375
  region: -5.882,3.1 -6.183,3.1 -6.183,2.375 -5.882,2.375
  rectangle: -5.548,-3.1 -5.247,-2.375
  region: -5.247,3.1 -5.548,3.1 -5.548,2.375 -5.247,2.375
  rectangle: -4.913,-3.1 -4.612,-2.375
  region: -4.612,3.1 -4.913,3.1 -4.913,2.375 -4.612,2.375
  rectangle: -4.278,-3.1 -3.977,-2.375
  region: -3.977,3.1 -4.278,3.1 -4.278,2.375 -3.977,2.375
  rectangle: -3.643,-3.1 -3.342,-2.375
  region: -3.342,3.1 -3.643,3.1 -3.643,2.375 -3.342,2.375
  rectangle: -3.008,-3.1 -2.707,-2.375
  region: -2.707,3.1 -3.008,3.1 -3.008,2.375 -2.707,2.375
  rectangle: -2.373,-3.1 -2.072,-2.375
  region: -2.072,3.1 -2.373,3.1 -2.373,2.375 -2.072,2.375
  rectangle: -1.738,-3.1 -1.437,-2.375
  region: -1.437,3.1 -1.738,3.1 -1.738,2.375 -1.437,2.375
  rectangle: -1.103,-3.1 -0.802,-2.375
  region: -0.802,3.1 -1.103,3.1 -1.103,2.375 -0.802,2.375
  rectangle: -0.468,-3.1 -0.167,-2.375
  region: -0.167,3.1 -0.468,3.1 -0.468,2.375 -0.167,2.375
  rectangle: 0.167,-3.1 0.468,-2.375
  region: 0.468,3.1 0.167,3.1 0.167,2.375 0.468,2.375
  rectangle: 0.802,-3.1 1.103,-2.375
  region: 1.103,3.1 0.802,3.1 0.802,2.375 1.103,2.375
  rectangle: 1.437,-3.1 1.738,-2.375
  region: 1.738,3.1 1.437,3.1 1.437,2.375 1.738,2.375
  rectangle: 2.072,-3.1 2.373,-2.375
  region: 2.373,3.1 2.072,3.1 2.072,2.375 2.373,2.375
  rectangle: 2.707,-3.1 3.008,-2.375
  region: 3.008,3.1 2.707,3.1 2.707,2.375 3.008,2.375
  rectangle: 3.342,-3.1 3.643,-2.375
  region: 3.643,3.1 3.342,3.1 3.342,2.375 3.643,2.375
  rectangle: 3.977,-3.1 4.278,-2.375
  region: 4.278,3.1 3.977,3.1 3.977,2.375 4.278,2.375
  rectangle: 4.612,-3.1 4.913,-2.375
  region: 4.913,3.1 4.612,3.1 4.612,2.375 4.913,2.375
  rectangle: 5.247,-3.1 5.548,-2.375
  region: 5.548,3.1 5.247,3.1 5.247,2.375 5.548,2.375
  rectangle: 5.882,-3.1 6.183,-2.375
  region: 6.183,3.1 5.882,3.1 5.882,2.375 6.183,2.375
  rectangle: 6.517,-3.1 6.818,-2.375
  region: 6.818,3.1 6.517,3.1 6.517,2.375 6.818,2.375
  rectangle: 7.152,-3.1 7.453,-2.375
  region: 7.453,3.1 7.152,3.1 7.152,2.375 7.453,2.375
  rectangle: 7.787,-3.1 8.088,-2.375
  region: 8.088,3.1 7.787,3.1 7.787,2.375 8.088,2.375
  rectangle: 8.422,-3.1 8.723,-2.375
  region: 8.723,3.1 8.422,3.1 8.422,2.375 8.723,2.375
  rectangle: 9.057,-3.1 9.358,-2.375
  region: 9.358,3.1 9.057,3.1 9.057,2.375 9.358,2.375
  rectangle: 9.692,-3.1 9.993,-2.375
  region: 9.993,3.1 9.692,3.1 9.692,2.375 9.993,2.375
  rectangle: 10.327,-3.1 10.628,-2.375
  region: 10.628,3.1 10.327,3.1 10.327,2.375 10.628,2.375
  lines w0.203: -14.045,-1.5 -14.045,1.5 ; -12.645,-2.4 12.645,-2.4 ; -12.645,2.4 12.645,2.4 ; -11.045,-2 11.045,-2 ; -11.045,-1 11.045,-1 ; -11.045,1 11.045,1 ; -11.045,2 11.045,2 ; 14.045,-1.5 14.045,1.5

## 53047-02 [mil]
pads (2):
  oval 27.5x55 hole 19.69: 1(24.61,17.72) 2(-24.61,17.72)
Top Overlay:
  rectangle: -78.74,-59.06 78.74,-44.29
  lines w2: -78.74,-9.84 -63.98,-9.84 -63.98,-49.21 ; -78.74,14.76 -63.98,14.76 -63.98,44.29 ; -73.82,54.13 -63.98,44.29 ; 63.98,-49.21 63.98,-9.84 78.74,-9.84 ; 73.82,54.13 63.98,44.29 ; 78.74,14.76 63.98,14.76 63.98,44.29 ; -63.98,44.29 63.98,44.29
  lines w8: -79.72,-59.06 79.72,-59.06 79.72,59.06 -79.72,59.06 -79.72,-59.06

## 53047-03 [mil]
pads (3):
  oval 27.5x55 hole 19.69: 1(49.21,17.72) 2(0,17.72) 3(-49.21,17.72)
Top Overlay:
  rectangle: -103.35,-59.06 103.35,-44.29
  lines w2: -103.35,-9.84 -88.58,-9.84 -88.58,-49.21 ; -103.35,14.76 -88.58,14.76 -88.58,44.29 ; -98.43,54.13 -88.58,44.29 ; 88.58,-49.21 88.58,-9.84 103.35,-9.84 ; 98.43,54.13 88.58,44.29 ; 103.35,14.76 88.58,14.76 88.58,44.29 ; -88.58,44.29 88.58,44.29
  lines w8: -104.33,-59.06 104.33,-59.06 104.33,59.06 -104.33,59.06 -104.33,-59.06

## 53047-04 [mil]
pads (4):
  oval 27.5x55 hole 19.69: 1(73.82,17.72) 2(24.61,17.72) 3(-24.61,17.72) 4(-73.82,17.72)
Top Overlay:
  rectangle: -127.95,-59.06 127.95,-44.29
  lines w2: -127.95,-9.84 -113.19,-9.84 -113.19,-49.21 ; -127.95,14.76 -113.19,14.76 -113.19,44.29 ; -123.03,54.13 -113.19,44.29 ; 113.19,-49.21 113.19,-9.84 127.95,-9.84 ; 123.03,54.13 113.19,44.29 ; 127.95,14.76 113.19,14.76 113.19,44.29 ; -113.19,44.29 113.19,44.29
  lines w8: -128.94,-59.06 128.94,-59.06 128.94,59.06 -128.94,59.06 -128.94,-59.06

## 53047-05 [mil]
pads (5):
  oval 27.5x55 hole 19.69: 1(98.43,17.72) 2(49.21,17.72) 3(0,17.72) 4(-49.21,17.72) 5(-98.43,17.72)
Top Overlay:
  rectangle: -152.56,-59.06 152.56,-44.29
  lines w2: -152.56,-9.84 -137.8,-9.84 -137.8,-49.21 ; -152.56,14.76 -137.8,14.76 -137.8,44.29 ; -147.64,54.13 -137.8,44.29 ; 137.8,-49.21 137.8,-9.84 152.56,-9.84 ; 147.64,54.13 137.8,44.29 ; 152.56,14.76 137.8,14.76 137.8,44.29 ; -137.8,44.29 137.8,44.29
  lines w8: -153.54,-59.06 153.54,-59.06 153.54,59.06 -153.54,59.06 -153.54,-59.06

## 53047-06 [mil]
pads (6):
  oval 27.5x55 hole 19.69: 1(123.03,17.72) 2(73.82,17.72) 3(24.61,17.72) 4(-24.61,17.72) 5(-73.82,17.72) 6(-123.03,17.72)
Top Overlay:
  rectangle: -177.17,-59.06 177.17,-44.29
  lines w2: -177.17,-9.84 -162.4,-9.84 -162.4,-49.21 ; -177.17,14.76 -162.4,14.76 -162.4,44.29 ; -172.24,54.13 -162.4,44.29 ; 162.4,-49.21 162.4,-9.84 177.17,-9.84 ; 172.24,54.13 162.4,44.29 ; 177.17,14.76 162.4,14.76 162.4,44.29 ; -162.4,44.29 162.4,44.29
  lines w8: -178.15,-59.06 178.15,-59.06 178.15,59.06 -178.15,59.06 -178.15,-59.06

## 53047-07 [mil]
pads (7):
  oval 27.5x55 hole 19.69: 1(147.64,17.72) 2(98.43,17.72) 3(49.21,17.72) 4(0,17.72) 5(-49.21,17.72) 6(-98.43,17.72) 7(-147.64,17.72)
Top Overlay:
  rectangle: -201.77,-59.06 201.77,-44.29
  lines w2: -201.77,-9.84 -187.01,-9.84 -187.01,-49.21 ; -201.77,14.76 -187.01,14.76 -187.01,44.29 ; -196.85,54.13 -187.01,44.29 ; 187.01,-49.21 187.01,-9.84 201.77,-9.84 ; 196.85,54.13 187.01,44.29 ; 201.77,14.76 187.01,14.76 187.01,44.29 ; -187.01,44.29 187.01,44.29
  lines w8: -202.76,-59.06 202.76,-59.06 202.76,59.06 -202.76,59.06 -202.76,-59.06

## 53047-08 [mil]
pads (8):
  oval 27.5x55 hole 19.69: 1(172.24,17.72) 2(123.03,17.72) 3(73.82,17.72) 4(24.61,17.72) 5(-24.61,17.72) 6(-73.82,17.72) 7(-123.03,17.72) 8(-172.24,17.72)
Top Overlay:
  rectangle: -226.38,-59.06 226.38,-44.29
  lines w2: -226.38,-9.84 -211.61,-9.84 -211.61,-49.21 ; -226.38,14.76 -211.61,14.76 -211.61,44.29 ; -221.46,54.13 -211.61,44.29 ; 211.61,-49.21 211.61,-9.84 226.38,-9.84 ; 221.46,54.13 211.61,44.29 ; 226.38,14.76 211.61,14.76 211.61,44.29 ; -211.61,44.29 211.61,44.29
  lines w8: -227.36,-59.06 227.36,-59.06 227.36,59.06 -227.36,59.06 -227.36,-59.06

## 53047-09 [mil]
pads (9):
  oval 27.5x55 hole 19.69: 1(196.85,17.72) 2(147.64,17.72) 3(98.43,17.72) 4(49.21,17.72) 5(0,17.72) 6(-49.21,17.72) 7(-98.43,17.72) 8(-147.64,17.72) 9(-196.85,17.72)
Top Overlay:
  rectangle: -250.98,-59.06 250.98,-44.29
  lines w2: -250.98,-9.84 -236.22,-9.84 -236.22,-49.21 ; -250.98,14.76 -236.22,14.76 -236.22,44.29 ; -246.06,54.13 -236.22,44.29 ; 236.22,-49.21 236.22,-9.84 250.98,-9.84 ; 246.06,54.13 236.22,44.29 ; 250.98,14.76 236.22,14.76 236.22,44.29 ; -236.22,44.29 236.22,44.29
  lines w8: -251.97,-59.06 251.97,-59.06 251.97,59.06 -251.97,59.06 -251.97,-59.06

## 53047-10 [mil]
pads (10):
  oval 27.5x55 hole 19.69: 1(221.46,17.72) 2(172.24,17.72) 3(123.03,17.72) 4(73.82,17.72) 5(24.61,17.72) 6(-24.61,17.72) 7(-73.82,17.72) 8(-123.03,17.72) 9(-172.24,17.72) 10(-221.46,17.72)
Top Overlay:
  rectangle: -275.59,-59.06 275.59,-44.29
  lines w2: -275.59,-9.84 -260.83,-9.84 -260.83,-49.21 ; -275.59,14.76 -260.83,14.76 -260.83,44.29 ; -270.67,54.13 -260.83,44.29 ; 260.83,-49.21 260.83,-9.84 275.59,-9.84 ; 270.67,54.13 260.83,44.29 ; 275.59,14.76 260.83,14.76 260.83,44.29 ; -260.83,44.29 260.83,44.29
  lines w8: -276.57,-59.06 276.57,-59.06 276.57,59.06 -276.57,59.06 -276.57,-59.06

## 53047-11 [mil]
pads (11):
  oval 27.5x55 hole 19.69: 1(246.06,17.72) 2(196.85,17.72) 3(147.64,17.72) 4(98.43,17.72) 5(49.21,17.72) 6(0,17.72) 7(-49.21,17.72) 8(-98.43,17.72) 9(-147.64,17.72) 10(-196.85,17.72) 11(-246.06,17.72)
Top Overlay:
  rectangle: -300.2,-59.06 300.2,-44.29
  lines w2: -300.2,-9.84 -285.43,-9.84 -285.43,-49.21 ; -300.2,14.76 -285.43,14.76 -285.43,44.29 ; -295.28,54.13 -285.43,44.29 ; 285.43,-49.21 285.43,-9.84 300.2,-9.84 ; 295.28,54.13 285.43,44.29 ; 300.2,14.76 285.43,14.76 285.43,44.29 ; -285.43,44.29 285.43,44.29
  lines w8: -301.18,-59.06 301.18,-59.06 301.18,59.06 -301.18,59.06 -301.18,-59.06

## 53047-12 [mil]
pads (12):
  oval 27.5x55 hole 19.69: 1(270.67,17.72) 2(221.46,17.72) 3(172.24,17.72) 4(123.03,17.72) 5(73.82,17.72) 6(24.61,17.72) 7(-24.61,17.72) 8(-73.82,17.72) 9(-123.03,17.72) 10(-172.24,17.72) 11(-221.46,17.72) 12(-270.67,17.72)
Top Overlay:
  rectangle: -324.8,-59.06 324.8,-44.29
  lines w2: -324.8,-9.84 -310.04,-9.84 -310.04,-49.21 ; -324.8,14.76 -310.04,14.76 -310.04,44.29 ; -319.88,54.13 -310.04,44.29 ; 310.04,-49.21 310.04,-9.84 324.8,-9.84 ; 319.88,54.13 310.04,44.29 ; 324.8,14.76 310.04,14.76 310.04,44.29 ; -310.04,44.29 310.04,44.29
  lines w8: -325.79,-59.06 325.79,-59.06 325.79,59.06 -325.79,59.06 -325.79,-59.06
